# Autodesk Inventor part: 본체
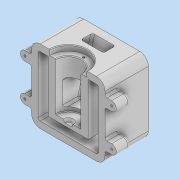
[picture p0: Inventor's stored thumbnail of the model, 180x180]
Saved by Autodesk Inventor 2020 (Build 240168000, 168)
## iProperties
Created: 2022-03
Part Number: 본체
Material: 일반
Document SubType Name: Modeling
Designer: Administrator
Density: 1 g/cm^3
Appearance: 기본값
Author: Administrator
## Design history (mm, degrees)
sketch "스케치1"
  geometry: L1 (-55, -55)-(55, -55); L2 (55, -55)-(55, 55); L3 (55, 55)-(-55, 55); L4 (-55, 55)-(-55, -55); L5 (-55, -55)-(55, 55); L6 (55, -55)-(-55, 55); 1 further point
  constraints: 12 end point, 2 midpoint, 2 parallel, 1 horizontal, 1 perpendicular
  dimensions: "d0" = 110 distance of L2.end L3.end; "d1" = 110 distance of L1.end L2.end
extrude "돌출1" new body sketch "스케치1" distance "d2" = 65; taper "d3" = 0 deg
node "작업 평면1"
sketch "스케치2"
  geometry: L1 (45, 45)-(45, -45); L2 (45, -45)-(-45, -45); L3 (-45, -45)-(-45, 45); L4 (-45, 45)-(-30, 45); L5 (-30, 45)-(-30, -33); L6 (-30, -33)-(30, -33); L7 (30, -33)-(30, 45); L8 (30, 45)-(45, 45); L9 (-55, -55)-(55, -55) reference; L10 (55, -55)-(55, 55) reference; L11 (-55, 55)-(-55, -55) reference; L12 (55, 55)-(-55, 55) reference; 1 further point
  constraints: 16 end point, 5 perpendicular, 2 vertical, 1 horizontal
  dimensions: "d5" = 10 distance between parallel lines of L2 L9; "d6" = 22 distance between parallel lines of L6 L9; "d7" = 10 distance between parallel lines of L1 L10; "d8" = 25 distance between parallel lines of L7 L10; "d9" = 10 distance between parallel lines of L3 L11; "d10" = 25 distance between parallel lines of L5 L11; "d11" = 10 distance between parallel lines of L4 L12; "d12" = 10 distance between parallel lines of L8 L12
extrude "돌출2" cut sketch "스케치2" distance "d13" = 104.5; taper "d14" = 0 deg
sketch "스케치3"
  geometry: L1 (-30, 22)-(-9.1, 100); L2 (-65, 100)-(0, 100) reference; L3 (0, 100)-(0, 22) reference; L4 (-65, 22)-(0, 22) reference; 1 further point
  constraints: 2 end point, 2 point on line
  dimensions: "d15" = 75 deg angle of L4 L1; "d16" = 30 horizontal distance of point (0, 55) L1.start
extrude "돌출3" cut sketch "스케치3" distance "d17" = 80; taper "d18" = 0 deg
sketch "스케치4"
  geometry: L1 (110, -65)-(0, -65) reference; 3 further points
  constraints: 1 coincident, 1 midpoint
hole "구멍1" sketch "스케치4" at (55, -65) diameter "d19" = 38; stored, may be unused: countersink angle "d23" = 90 deg, drill point angle "d25" = 0 deg; dims "d20" = 8, "d21" = 56, "d22" = 8, "d24" = 80
sketch "스케치5"
  geometry: L1 (19, 0)-(-19, 0) reference; C1 r 7.5 at (0, 0); 2 further points
  constraints: 1 centre point, 1 coincident, 1 midpoint
  dimensions: "d26" = 15 diameter of C1
extrude "돌출4" new body sketch "스케치5" distance "d27" = 4; taper "d28" = 0 deg
feature "면 기울기1" dims angle "d29" = -30 deg
feature "결합1"
  node "솔리드2"
sketch "스케치8"
  geometry: L1 (45, 9.1)-(-33, 30) reference; L2 (55, 11.597)-(-19, 31.425); L3 (55, 29.197)-(-19, 49.025); L4 (55, 0)-(55, 65) reference; L5 (-19, 49.025)-(-19, 31.425); 1 further point
  constraints: 6 end point, 2 parallel, 2 point on line, 1 vertical
  dimensions: "d39" = 5 distance between parallel lines of L1 L2; "d40" = 17 distance between parallel lines of L2 L3; "d41" = 74 distance between parallel lines of L5 L4
extrude "돌출7" cut sketch "스케치8" stored distance "d42" = 34; taper "d43" = 0 deg
sketch "스케치9"
  geometry: L1 (17, -19)-(-17, -19); L2 (-17, -19)-(-17, 19); L3 (-17, 19)-(17, 19); L4 (17, 19)-(17, -19); L5 (-28, 55)-(-55, 55) reference; 2 further points
  constraints: 8 end point, 2 parallel, 1 horizontal, 1 midpoint, 1 perpendicular, 1 vertical alignment
  dimensions: "d44" = 34 distance of L2.end L3.end; "d45" = 36 distance between parallel lines of L3 L5; "d46" = 38 distance of L1.end L2.end
extrude "돌출8" cut sketch "스케치9" stored distance "d47" = 34; taper "d48" = 0 deg
sketch "스케치10"
  geometry: L1 (-55, -55)-(55, -55) reference; L2 (65, -35)-(45, -35); L3 (65, -21)-(45, -21); L4 (45, 45)-(45, -45) reference; L5 (65, 21)-(45, 21); L6 (65, 35)-(45, 35); L7 (0, 0)-(0, 78.566); L8 (-65, -35)-(-45, -35); L9 (-65, -21)-(-45, -21); L10 (-65, 21)-(-45, 21); L11 (-65, 35)-(-45, 35); L12 (-45, -45)-(-45, 45) reference; A1 r 7 centre (65, -28) between (65, -35) and (65, -21); A2 r 7 centre (65, 28) between (65, 21) and (65, 35); A3 r 7 centre (-65, -28) between (-65, -21) and (-65, -35); A4 r 7 centre (-65, 28) between (-65, 35) and (-65, 21)
  constraints: 18 end point, 10 symmetric about line, 8 point on circle, 4 centre point, 4 point on line, 4 tangent, 3 horizontal, 1 equal radius, 1 perpendicular, 1 vertical, 1 vertical alignment, 2 other
  dimensions: "d49" = 14 diameter of A1; "d50" = 27 distance from line of A1.centre L1; "d51" = 56 distance of A2.centre A1.centre; "d52" = 65 horizontal distance of L7.start A1.centre
extrude "돌출9" join sketch "스케치10" distance "d53" = 20; taper "d54" = 0 deg
sketch "스케치11"
  geometry: A1 r 28 centre (0, 0) between (28, 0) and (-28, 0) reference; 2 further points
  constraints: 1 vertical alignment
  dimensions: "d55" = 23 distance of A1.centre point (0, 23)
hole "구멍2" sketch "스케치11" at (0, 23) diameter "d56" = 3.242; stored, may be unused: countersink angle "d60" = 90 deg, drill point angle "d62" = 118 deg; dims "d57" = 9, "d58" = 56, "d59" = 8, "d61" = 11
sketch "스케치12"
  geometry: A1 r 7 centre (65, -28) between (65, -35) and (65, -21) reference; A2 r 7 centre (65, 28) between (65, 21) and (65, 35) reference; A3 r 7 centre (-65, 28) between (-65, 35) and (-65, 21) reference; A4 r 7 centre (-65, -28) between (-65, -21) and (-65, -35) reference; 5 further points
  constraints: 4 coincident
hole "구멍3" sketch "스케치12" at (65, -28), (65, 28), (-65, 28), (-65, -28) diameter "d63" = 3.242; stored, may be unused: countersink angle "d67" = 90 deg, drill point angle "d69" = 118 deg; dims "d64" = 9, "d65" = 56, "d66" = 8, "d68" = 11
fillet "모깎기1" dims "d70" = 1
fillet "모깎기2" dims "d71" = 1
fillet "모깎기3" dims "d72" = 3
fillet "모깎기4" dims "d73" = 13
fillet "모깎기5" dims "d74" = 3
fillet "모깎기6" dims "d75" = 3
fillet "모깎기7" dims "d76" = 3
chamfer "모따기1" distance "d77" = 1; stored, may be unused: second distance "d78" = 2, angle "d79" = 45 deg
sketch "스케치13"
  geometry: L1 (-65, 60)-(-65, -24) reference; L2 (0, 73)-(-65, 73) reference; 2 further points
  constraints: 1 other
  dimensions: "d80" = 20 distance from line of point (-45, 18) L1; "d81" = 55 distance from line of point (-45, 18) L2
feature "엠보싱1" sketch "스케치13" dims "d0" = 110, "d1" = 110, "d82" = 0.5, "d83" = 0
node "솔리드1"
feature "A9D066F2-1C7D-4E18-AEED-F7BC21143FA4" dims "d19" = 38, "d20" = 8, "d21" = 56, "d22" = 8, "d23" = 90 deg, "d24" = 80, "d25" = 0
